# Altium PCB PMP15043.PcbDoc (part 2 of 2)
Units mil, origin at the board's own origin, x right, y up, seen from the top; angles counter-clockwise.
Board outline 3400 x 1800 mil, 4 copper layers (Top Layer, Signal Layer 1, Signal Layer 2, Bottom Layer), stack 60.634 mil thick; 118 components, 63 nets, 326 pads, 97 vias.
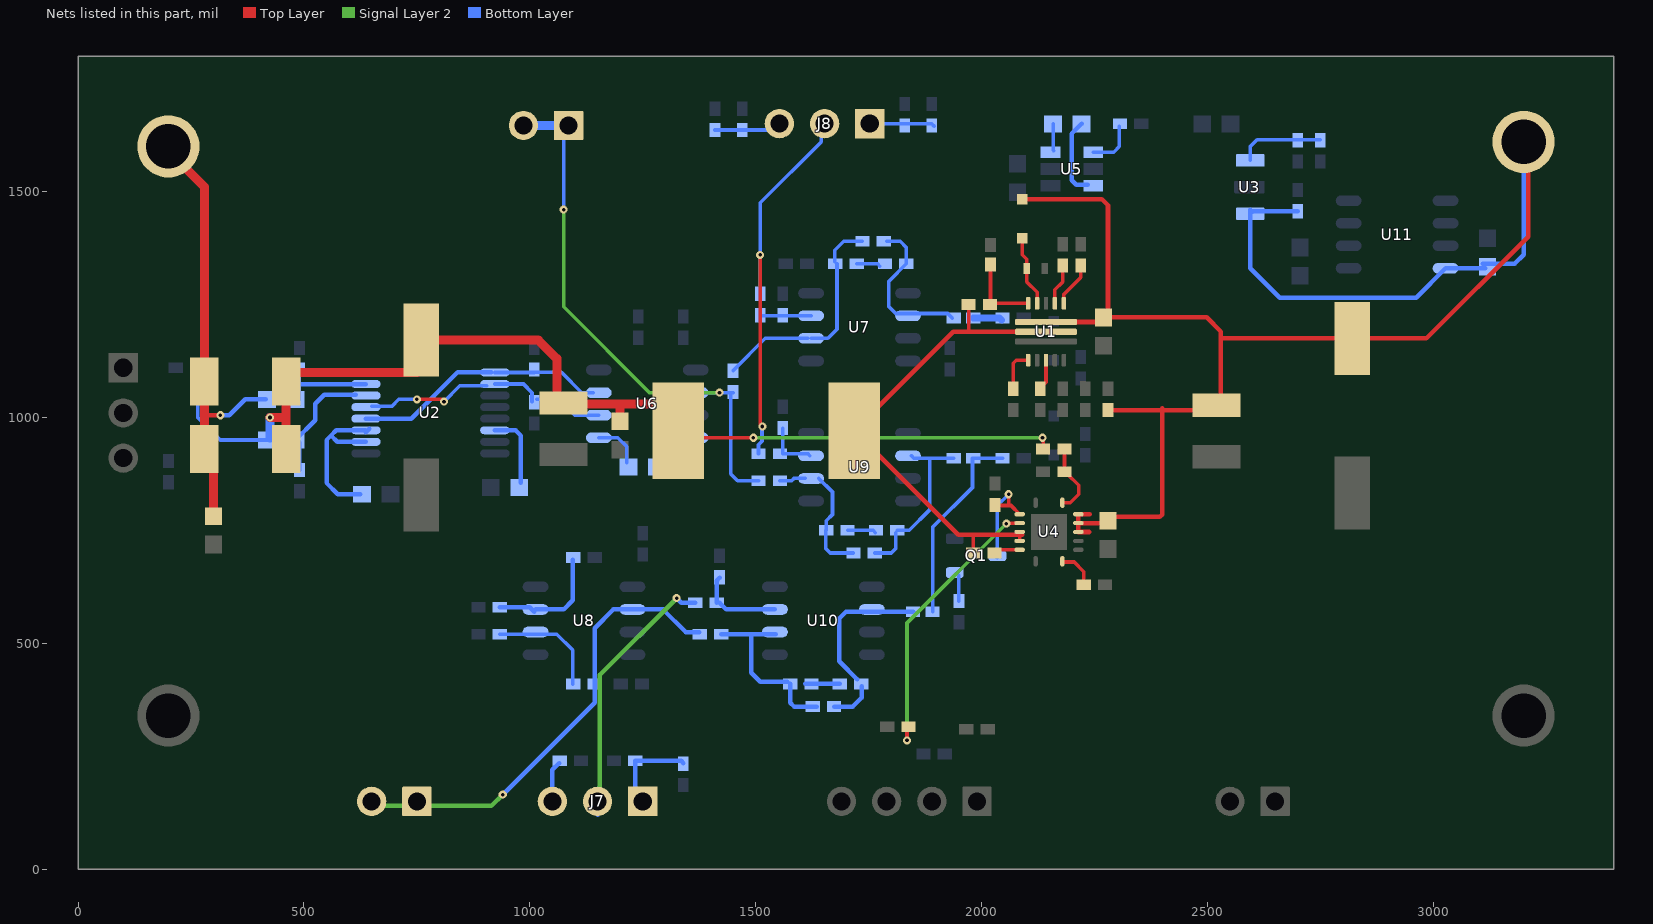
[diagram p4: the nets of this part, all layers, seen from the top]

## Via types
v1: diameter 18, hole 8, Top Layer to Bottom Layer, 93 vias
v2: diameter 19.68, hole 8, Top Layer to Bottom Layer, 4 vias

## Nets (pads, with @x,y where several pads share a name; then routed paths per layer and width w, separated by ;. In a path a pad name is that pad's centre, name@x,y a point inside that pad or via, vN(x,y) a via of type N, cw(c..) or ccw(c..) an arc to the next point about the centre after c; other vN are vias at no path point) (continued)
IBAT: J9.1 J9.2 R23.2 R30.1 U6.6 | length 1259.5
  Signal Layer 2 w8: v1@1075,1465 v1(1075,1460) 1075,1245 1265,1055 v1(1420,1055)
  Bottom Layer w8: v1(1075,1460) J9.1@1075,1635 ; U6.6@1367.28,1055 v1(1420,1055) R23.2@1445,1055 ; R23.2@1450,1055 R23.2@1445,1055 ; R30.1@1506.38,860 1460,860 1445,875 R23.2@1445,1055
  Bottom Layer w20: J9.2@985.91,1646.4 J9.1@1085.91,1646.4 J9.1@1096.4,1646.4
ISEN+: C25.1 U2.1 U2.12 U6.3 | length 556.4
  Bottom Layer w8: U2.1@922.72,1099.57 1009.57,1099.57 1010,1100 1070,1100 1115,1055 U6.3@1140,1055
  Bottom Layer w10: U2.12@637.28,997.2 737.2,997.2 840,1100 U2.1@915,1100
ISEN-: C23.1 U2.2 U2.13 U6.2 | length 533.1
  Top Layer w8: v1(750,1040) v1@805,1040
  Bottom Layer w8: U2.13@650,1025 695,1025 710,1040 v1(750,1040) ; v1(810,1035) 845,1070 U2.2@905,1070 ; U2.2@922.72,1073.98 986.02,1073.98 1005,1055 C23.1@1005,1035 ; C23.1@1015,1040 1065,1040 1100,1005 U6.2@1152.72,1005
ISET: J8.2 R26.2 R36.2 | length 869.5
  Top Layer w8: v1@1510,985 v1(1510,1360)
  Bottom Layer w8: R36.2@1506.38,920 1506.38,939.51 1514,947.13 v1@1514,984 ; R26.2@1510,1273.62 v1(1510,1360) 1510,1475 1645,1610 J8.2@1645,1645
  other v1: 1515,980
NetC3_1: C3.1 J1.1 R1.1 R2.1 R7.2 | length 970.3
  Top Layer w10: 285,1005 v1(315,1005)
  Top Layer w20: J1.1@190,1600 279.45,1510.55 R1.1@279.45,1080 ; R2.1@279.45,930 279.45,1079.45 R1.1@280,1080 ; C3.1@300,781.5 R2.1@300,900
  Bottom Layer w10: v1(315,1005) 335,1005 370,1040 R7.2@415,1040
NetC5_2: C5.2 D1.2 U1.12 | length 156.1
  Top Layer w8: D1.2@2090,1395 2090,1360 2100,1350 C5.2@2100,1330 2100,1300 2123.08,1276.92 U1.12@2123.08,1252.63
NetC6_2: C6.2 D2.1 U1.13 | length 167.8
  Top Layer w8: C6.2@2020,1253.62 2020,1335 D2.1@2025,1340 ; C6.2@2025,1255 2027.37,1252.63 U1.13@2103.39,1252.63
NetC7_1: C7.1 U1.10 | length 84.6
  Top Layer w8: U1.10@2162.45,1252.63 2162.45,1282.45 2180,1300 C7.1@2180,1330
NetC11_1: C11.1 R7.1 U2.15 | length 212.6
  Bottom Layer w8: R7.1@490,1040 C11.1@490,1106.38
  Bottom Layer w10: 491.02,1073.98 U2.15@637.28,1073.98
NetC12_1: C12.1 R8.1 U2.14 | length 257.7
  Bottom Layer w10: R8.1@481.5,950 525,993.5 525,1030 545,1050 585,1050 U2.14@615,1050 ; C12.1@490,883.62 R8.1@490,945
NetC16_1: C16.1 U4.13 | length 50.3
  Top Layer w8: C16.1@2035,705 2037.06,707.06 U4.13@2084.44,707.06
NetC17_1: C17.1 Q1.3 U4.9 | length 234.8
  Top Layer w8: C17.1@2035,810 2040,805 2060,805 ; v1(2060,830) 2060,805 ; U4.9@2084.44,785.8 2065.25,805 2060,805
  Bottom Layer w8: Q1.3@2035,690 2035,735 2035,805 v1(2060,830)
NetC18_1: C18.1 U5.6 | length 173
  Bottom Layer w10: C18.1@2221.5,1650 2200,1628.5 2200,1525 2210,1515 U5.6@2235,1515
NetC18_2: C18.2 U5.3 | length 60.6
  Bottom Layer w8: C18.2@2158.5,1650 2158.5,1591.5 U5.3@2160,1590
NetC20_1: C20.1 C22.1 D3.1 U7.6 | length 347
  Bottom Layer w8: C20.1@1790,1390 1820,1390 1833.62,1376.38 C22.1@1833.62,1340 1795,1301.38 1795,1245 1810,1230 1925,1230 D3.1@1935,1220
NetC20_2: C20.2 R22.1 R23.1 U7.2 | length 499.8
  Bottom Layer w8: R23.1@1450,1103.62 1521.38,1175 U7.2@1615,1175 ; U7.2@1622.72,1175 1660,1175 1680,1195 R22.1@1680,1340 ; R22.1@1675,1345 1675,1370 1695,1390 C20.2@1736.38,1390
NetC22_2: C22.2 R22.2 | length 53.4
  Bottom Layer w8: R22.2@1723.62,1340 1770,1340 C22.2@1775,1335
NetC26_1: C26.1 R26.1 U7.3 | length 112.7
  Bottom Layer w8: R26.1@1510,1225 U7.3@1622.72,1225
NetC28_1: C28.1 C30.1 D5.1 U9.6 | length 386
  Bottom Layer w8: C28.1@1763.62,700 1800,700 1810,710 C30.1@1810,745 ; C30.1@1813.62,750 1840,750 1885,795 1885,910 ; U9.6@1845,915 1850,910 1885,910 ; D5.1@1938.35,910 1885,910
NetC28_2: C28.2 R27.1 R30.2 U9.2 | length 297
  Bottom Layer w8: R30.2@1553.62,860 1580,860 1585,865 U9.2@1610,865 ; U9.2@1640,865 1670,835 1670,785 1656.38,771.38 R27.1@1656.38,750 ; R27.1@1655,750 1655,710 1665,700 C28.2@1716.38,700
NetC29_1: C29.1 C31.1 D7.1 U10.6 | length 415.8
  Bottom Layer w10: C29.1@1673.62,360 1715,360 1735,380 C31.1@1735,405 ; C31.1@1725,420 1685,460 1685,555 1700,570 D7.1@1848.35,570
NetC29_2: C29.2 R31.1 R35.2 U10.2 | length 398.2
  Bottom Layer w10: R35.2@1423.62,520 1490,520 ; U10.2@1545,520 1490,520 ; R31.1@1570,415 1510,415 1490,435 1490,520 ; R31.1@1576.38,410 1576.38,368.62 1585,360 C29.2@1626.38,360 C29.2@1635,360
NetC30_2: C30.2 R27.2 | length 63.4
  Bottom Layer w8: R27.2@1703.62,750 1760,750 C30.2@1765,745
NetC31_2: C31.2 R31.2 | length 76.4
  Bottom Layer w10: R31.2@1610,410 R31.2@1623.62,410 C31.2@1686.38,410
NetC33_1: C33.1 R36.1 U9.3 | length 118.4
  Bottom Layer w8: C33.1@1560,976.38 1560,920 1615,920 U9.3@1620,915
NetC34_1: C34.1 R39.1 U10.3 | length 186.6
  Bottom Layer w10: R39.1@1413.62,590 1413.62,638.62 C34.1@1420,645 ; R39.1@1420,590 1435,575 U10.3@1542.72,575
NetD3_2: D3.2 R25.2 | length 65.4
  Bottom Layer w15: D3.2@1981.65,1220 2040,1220 R25.2@2045,1215
NetD5_2: D5.2 D7.2 R34.2 | length 443
  Bottom Layer w8: D7.2@1891.65,570 1891.65,756.65 1980,845 1980,910 D5.2@1981.65,910 R34.2@2046.38,910
NetJ7_1: J7.1 R42.1 R44.2 | length 182.1
  Bottom Layer w10: J7.1@1233.62,166.38 R42.1@1233.62,240 1335,240 R44.2@1340,235
NetJ7_3: J7.3 R40.1 | length 91.2
  Bottom Layer w10: J7.3@1050,150 1050,220 R40.1@1065,235
NetJ8_1: J8.1 R43.1 R45.2 | length 144.6
  Bottom Layer w8: J8.1@1752.61,1650.34 1889.66,1650.34 R45.2@1895,1645
NetJ8_3: J8.3 R41.1 R46.2 | length 135.6
  Bottom Layer w8: R46.2@1410,1636.38 1526.38,1636.38 J8.3@1540,1650
NetQ1_1: Q1.1 R19.2 | length 56.4
  Bottom Layer w8: R19.2@1950,593.62 Q1.1@1950,650
NetR4_2: R4.2 U1.1 | length 81.1
  Top Layer w8: R4.2@2070,1075 2070,1120 2076.65,1126.65 U1.1@2103.39,1126.65
NetR5_1: R5.1 U1.9 | length 93.1
  Top Layer w8: U1.9@2182.13,1252.63 2182.13,1272.13 2220,1310 R5.1@2220,1330
NetR6_2: R6.2 U1.3 | length 52.8
  Top Layer w8: R6.2@2140,1075 2142.76,1077.76 U1.3@2142.76,1126.65
NetR12_1: R12.1 R13.2 U3.1 | length 192.2
  Bottom Layer w8: U3.1@2594.8,1569.06 2594.8,1599.8 2610,1615 R13.2@2750,1615
NetR14_2: R14.2 U2.10 U2.11 | length 370.6
  Bottom Layer w10: R14.2@625,830 575,830 550,855 550,950 560,960 ; U2.10@637.28,946.02 573.98,946.02 560,960 ; U2.11@637.28,967.28 U2.11@645,975 ; U2.11@637.28,971.61 571.61,971.61 560,960
NetR15_2: R15.2 U2.6 | length 167.1
  Bottom Layer w10: U2.6@922.72,971.61 968.39,971.61 980,960 R15.2@980,855
NetR16_2: R16.2 U4.10 | length 629.5
  Top Layer w8: v1(1835,285) R16.2@1835,315 ; v1@2056.12,766.12 U4.10@2084.44,766.12
  Signal Layer 2 w8: v1(1835,285) 1835,545 v1(2055,765)
NetR17_2: R17.2 R18.2 U4.7 | length 150.6
  Top Layer w8: U4.7@2178.94,811.39 2196.39,811.39 2215,830 2215,850 R18.2@2190,875 ; R18.2@2180,880 2183.62,883.62 R17.2@2183.62,930
NetR20_1: R20.1 U5.4 | length 108
  Bottom Layer w8: U5.4@2247.24,1587.4 2292.4,1587.4 2305,1600 R20.1@2305,1645
NetR21_2: R21.2 U4.1 | length 83.9
  Top Layer w8: U4.1@2180,680 2205,680 2226.38,658.62 2226.38,641.81 R21.2@2226.38,630
NetR24_1: R24.1 U6.8 | length 127.7
  Bottom Layer w8: R24.1@1281.5,890 1281.5,931.5 1300,950 U6.8@1360,950
NetR24_2: R24.2 U6.1 | length 105.6
  Bottom Layer w8: U6.1@1152.72,955 1195,955 1215,935 R24.2@1215,900
NetR29_1: R29.1 R32.2 U8.2 | length 250.9
  Bottom Layer w8: R32.2@933.62,520 1060,520 1095,485 R29.1@1095,410
NetR33_2: R33.2 R38.2 U8.3 | length 261.1
  Bottom Layer w10: R33.2@933.62,580 1000,580 U8.3@1010,570 ; U8.3@1012.72,575 1075,575 1095,595 R38.2@1095,685
SW: C6.1 C16.2 L1.2 U1.7@2142.76,1189.64 U4.11 U4.12 | length 1068.5
  Top Layer w8: 1971.38,1191.38 C6.1@1971.38,1250 ; C16.2@1981.38,700 1981.38,740 1981.38,741.38 ; U4.12@2084.44,726.75 2084.44,740 2084.44,744.44 U4.11@2085,745
  Top Layer w10: 2090,740 2084.44,740 1981.38,740 1948.78,740 L1.2@1718.18,970.59 1937.59,1190 U1.7@2110,1190
VBAT: J12.1 J12.2 R29.2 R35.1 U8.6 | length 1022.5
  Signal Layer 2 w10: J12.2@650,140 750,140 915,140 v1(940,165)
  Bottom Layer w10: v1(940,165) 1143.62,368.62 R29.2@1143.62,410 1143.62,533.62 1185,575 U8.6@1227.28,575 1295,575 1345,525 R35.1@1375,525
VBUS: C8.1 C9.1 C10.1 C13.1 C15.1 C39.1 D1.1 J3.1 R9.2 U1.8@2142.76,1211.29 U3.3 U4.4 U4.5 U4.6 U11.8 | length 3869.7
  Top Layer w10: D1.1@2090,1483.31 2266.69,1483.31 2280,1470 C8.1@2280,1221.5 ; U1.8@2142.76,1211.29 2278.71,1211.29 C8.1@2280,1210 ; U4.6@2214.37,785.8 2239.2,785.8 ; U4.6@2215,785 2214.37,784.37 U4.5@2214.37,766.12 ; 2238.57,746.43 U4.4@2214.37,746.43 U4.5@2214.37,766.12 ; C15.1@2265,765 2263.88,766.12 U4.5@2214.37,766.12 ; C8.1@2270,1221.5 C8.1@2280,1221.5 ; C15.1@2278.5,770 C15.1@2280,771.5 2288.5,780 2395,780 2400,785 2400,1016.38 ; R9.2@2280,1016.38 2400,1016.38 ; C8.1@2280,1220 C8.1@2280,1221.5 ; 2400,1020 2400,1016.38 ; C9.1@2490,1015 2488.62,1016.38 2400,1016.38 ; C9.1@2530,1030 2530,1190 2498.5,1221.5 C8.1@2280,1221.5 ; 2534.86,1174.86 C10.1@2820.96,1174.86 2984.86,1174.86 3210,1400 J3.1@3210,1620
  Bottom Layer w10: U3.3@2595,1460 2595,1330 2660,1265 2962.28,1265 U11.8@3027.28,1330 C39.1@3115,1330 ; U3.3@2600,1455 2601.38,1456.38 C13.1@2700,1456.38 ; C39.1@3110,1340 3180,1340 3200,1360 J3.1@3200,1610
VIN: C1.1 C2.1 C4.1 L1.1 R1.2 R2.2 R8.2 R17.1 R37.1 | length 2316.9
  Top Layer w8: L1.1@1370,955 v1(1495,955) ; R17.1@2136.38,930 v1@2136.38,953.62
  Top Layer w20: v1(425,1000) 460.55,1000 ; R1.2@460,1070 460.55,1069.45 460.55,1000 ; R2.2@460.55,930 460.55,1000 ; R1.2@460.55,1080 480.55,1100 C2.1@750,1100 ; C2.1@760,1171.26 1018.74,1171.26 1060,1130 1060,1030 1200,1030 ; C1.1@1200,991.5 1200,1030 ; L1.1@1330,1030 1200,1030
  Signal Layer 2 w8: v1(1495,955) v1(2135,955)
  Bottom Layer w8: R37.1@265,1110 265,1000 315,950 R8.2@418.5,950
  Bottom Layer w20: R8.2@425,955 v1(425,1000)
VSET: J7.2 R39.2 | length 595.9
  Signal Layer 2 w10: J7.2@1155,150 1155,430 v1(1325,600)
  Bottom Layer w10: J7.2@1150,120 J7.2@1150,150 ; v1(1325,600) 1335,590 R39.2@1366.38,590
pads on no net: J5.2 U1.6@2095.52,1167.98 U1.6@2142.76,1167.98 U1.6@2190.01,1167.98 U1.7@2095.52,1189.64 U1.7@2142.76,1189.64 U1.7@2190.01,1189.64 U1.8@2095.52,1211.29 U1.8@2142.76,1211.29 U1.8@2190.01,1211.29 U2.3 U2.4 U2.5 U4.14 U7.1 U7.5 U7.8 U8.1 U8.5 U8.8 U9.1 U9.5 U9.8 U10.1 U10.5 U10.8 U11.4 U11.5

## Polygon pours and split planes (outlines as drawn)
GND on Top Layer "TOP_LAYER_GND_P036" (solid, remove dead copper, pour order 36): 1960,350 2310,350 2335,375 2335,615 2285,665 1970,665 1945,640 1945,365 1960,350
SW on Top Layer "TOP_LAYER_SW_P034" (solid, remove dead copper, pour order 34): 1645,830 1645,390 1685,350 1865,350 1915,400 1915,815 1910,820
VIN on Top Layer "TOP_LAYER_VIN_P030" (solid, remove dead copper, pour order 30): 1495,865 1495,375 1470,350 1310,350 1265,395 1265,835 1340,910
NetC3_1 on Top Layer "TOP_LAYER_NETC3_1_P000" (solid, remove dead copper, pour order 0): 100,1525 100,1705 150,1755 245,1755 350,1650 350,855 330,835 195,835 185,845 185,1280 100,1365
VIN on Top Layer "TOP_LAYER_VIN_P002" (solid, remove dead copper, pour order 2): 430,875 430,1375 480,1425 1410,1425 1495,1340 1495,835 1460,800 1285,800 1265,820 1265,1005 1245,1025 665,1025 515,875
GND on Top Layer "TOP_LAYER_GND_P004" (solid, remove dead copper, pour order 4): 350,250 160,250 100,310 100,660 165,725 455,725 690,960 1150,960 1160,950 1160,615 795,250
SW on Top Layer "TOP_LAYER_SW_P006" (solid, remove dead copper, pour order 6): 2080,1185 2070,1195 2060,1205 2035,1230 1975,1230 1680,1230 1645,1195 1645,770 1690,725 2085,725 2085,750 2015,750 2000,765 2000,1075 1985,1090 1970,1105 1970,1165 1990,1185 2015,1185
GND on Top Layer "TOP_LAYER_GND_P008" (solid, remove dead copper, pour order 8): 2150,1175 1995,1175 1990,1170 1990,1105 2000,1095 2035,1095 2055,1115 2090,1150 2150,1150 2260,1150 2265,1155 2265,1175
GND on Top Layer "TOP_LAYER_GND_P010" (solid, remove dead copper, pour order 10): 2220,1175 2415,1175 2430,1160 2430,1100 2420,1090 2260,1090 2190,1160
VBUS on Top Layer "TOP_LAYER_VBUS_P012" (solid, remove dead copper, pour order 12): 2075,1205 2075,1225 2080,1230 2190,1230 2240,1280 2240,1415 2255,1430 2805,1430 2805,1215 2795,1205
VBUS on Top Layer "TOP_LAYER_VBUS_P014" (solid, remove dead copper, pour order 14): 2230,740 2230,920 2300,990 2310,1000 2310,1065 2320,1075 2460,1075 2460,815 2385,740
GND on Top Layer "TOP_LAYER_GND_P016" (solid, remove dead copper, pour order 16): 3300,250 3300,790 3150,940 2465,940 2465,800 2440,775 2395,730 2295,730 2260,730 2255,725 2255,675 2255,390 2395,250
VBUS on Top Layer "TOP_LAYER_VBUS_P018" (solid, remove dead copper, pour order 18): 2810,980 3125,980 3305,1160 3305,1665 3270,1700 2385,1700 2240,1555 2240,1390 2335,1295
GND on Bottom Layer "BOTTOM_LAYER_GND_P038" (solid, remove dead copper, pour order 38): 3160,1370 3160,1450 3020,1590 2780,1590 2775,1585 2750,1560 2750,1490 2750,1370 2755,1365
GND on Bottom Layer "BOTTOM_LAYER_GND_P026" (solid, remove dead copper, pour order 26): 3275,290 3275,1110 3150,1235 2335,1235 2265,1165 2265,905 2240,880 2145,880 2120,855 2120,715 2060,655 2060,340 2150,250 3225,250 3275,300
+5V on Bottom Layer "BOTTOM_LAYER_+5V_P020" (solid, remove dead copper, pour order 20): 2545,1505 2545,1610 2535,1620 2330,1620 2325,1615 2325,1390 2345,1370 2535,1370 2550,1385 2550,1505
GND on Signal Layer 2 "SIGNAL_LAYER_2_GND_P022" (solid, remove dead copper, pour order 22): 440,395 440,1260 720,1540 2195,1540 2295,1440 2295,420 2215,340 495,340 440,395
GND on Signal Layer 1 "SIGNAL_LAYER_1_GND_P024" (solid, remove dead copper, pour order 24): 410,390 410,1295 660,1545 2895,1545 2970,1470 2970,395 2880,305 495,305 410,390

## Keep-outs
Keep-Out Layer:
  text ".Layer_Name" at 577,-858.49 h60

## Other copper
Top Layer:
  rectangle net GND: 2240,655 2270,730
  rectangle net VBUS: 2450,980 2830,1220
  rectangle net GND: 2120,830 2190,855
  rectangle net GND: 2135,780 2165,840
  rectangle net GND: 2135,625 2165,715
  rectangle net GND: 2005,505 2195,640
  rectangle net GND: 2260,1090 2390,1175
  text ".Layer_Name" at 577,-858.49 h60
Signal Layer 2:
  pour cut-out: 2285,1195 2360,1195 2375,1180 2375,1085 2365,1075 2295,1075 2285,1085
  pour cut-out: 1990,1185 2070,1185 2080,1175 2080,1115 2060,1095 2005,1095 1990,1110
  pour cut-out: 2215,580 2215,835 2195,855 2095,855 2085,845 2085,660 2065,640 2065,590 2075,580
  pour cut-out: 1015,880 1030,895 1130,895 1140,885 1140,830 1130,820 1020,820 1015,825
Bottom Layer:
  rectangle net GND: 1030,830 1135,880
  rectangle net GND: 2110,580 2205,790
  rectangle net GND: 2075,580 2205,665
  rectangle net GND: 2120,735 2205,855
  rectangle net GND: 1975,1045 2095,1175
  text ".Layer_Name" at 577,-858.49 h60

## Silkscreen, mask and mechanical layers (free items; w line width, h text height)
Top Overlay:
  rectangle: 2050,1100 2070,1120
  rectangle: 2240,655 2260,670
  lines w10: 1530,15 1730,15 1790,75 1790,95 ; 1890,95 1890,70 1940,20 2215,20
  text "VBUS" at 2890,1580 h80
  text "BAT" at 325,1555 h80
  text "H" at 1525,1540 h60
  text "ISET" at 1600,1540 h60
  text "L" at 1745,1540 h60
  text "IBAT" at 980,1535 h60
  text "B+" at 75,1175 h60
  text "B-" at 75,810 h60
  text "GND" at 325,320 h80
  text "GND" at 2935,315 h80
  text "VBAT" at 640,220 h60
  text "VSET" at 1090,220 h60
  text "L" at 1250,220 h60
  text "5V" at 1640,220 h60
  text "H" at 1030,215 h60
  text "GND" at 1965,215 h60
  text "GND" at 2540,215 h60
  text "BUCK_EN" at 1960,40 h60
  text "BST_EN" at 1525,35 h60
  text ".Layer_Name" at 577,-858.49 h60
Bottom Overlay:
  rectangle: 1465,435 1505,475
  rectangle: 1530,740 1585,785
  rectangle: 1540,1115 1580,1160
  rectangle: 920,420 970,470
  rectangle: 1060,895 1110,945
  rectangle: 900,1155 955,1210
  text ".Layer_Name" at 577,-858.49 h60
Top Paste:
  text ".Layer_Name" at 577,-858.49 h60
Bottom Paste:
  text ".Layer_Name" at 577,-858.49 h60
Top Solder:
  text ".Layer_Name" at 577,-858.49 h60
  text ".Layer_Name" at 577,-858.49 h60
Bottom Solder:
  text ".Layer_Name" at 577,-858.49 h60
Drill Guide:
  text ".Layer_Name" at 577,-858.49 h60
M1 Board Outline:
  lines w2: 0,0 2950,0 3400,0 3400,1800 0,1800
  lines w5: 0,0 0,1800
  text ".Layer_Name" at 577,-858.49 h60
M2 Board Dimensions:
  rectangle: 0,-275 125,-150
  rectangle: 125,-400 500,-275
  lines w7: 0,-275 1000,-275 ; 125,-400 125,-150 ; 250,-400 250,-150 ; 500,-400 500,-150 ; 750,-400 750,-150 ; 0,-400 1000,-400 1000,-150 0,-150 0,-400
  text ".Layer_Name" at 577,-858.49 h60
M3 3D STEP Top:
  text ".Layer_Name" at 577,-858.49 h60
M4 3D STEP Bottom:
  text ".Layer_Name" at 577,-858.49 h60
M5 Assembly Top:
  lines w10: -292,-930.17 6308,-930.17 ; -292,-726.83 6310,-726.83 ; -292,-523.5 -292,-1133.5 3713,-1133.5 6310,-1133.5 6310,-523.5 -291.5,-523.5 -291.5,-1133.5 1284,-1133.5 ; 2173,-1133.5 2173,-523.5 ; 3440,-726.83 3440,-523.5 ; 4280,-726.83 4280,-523.5 ; 4902,-1140 4902,-937.17
  text "COMPONENTS MARKED 'DNP' SHOULD NOT BE POPULATED." at 1153.5,-318.5 h60
  text "ASSEMBLY VARIANT:" at 1153,-434 h60
  text ".VariantName" at 2189,-434 h60
  text "PCB VIEWED FROM TOP SIDE" at -228.5,-655.67 h60
  text "BOARD #:" at 2248,-655.67 h60
  text ".PRJ_Number" at 2793.5,-655.67 h60
  text "REV:" at 3638,-655.67 h60
  text ".PCB_Rev" at 3929.5,-655.67 h60
  text "SVN REV:" at 4476,-655.67 h60
  text ".VersionControl_RevNumber" at 4982,-655.67 h60
  text "TID #:" at 2248,-859 h60
  text ".TID" at 2793.5,-859 h60
  text "PLOT NAME =" at -228.5,-1064.34 h60
  text ".plot_File_Name" at 577,-1064.34 h60
  text "GENERATED    :" at 2250,-1064.34 h60
  text ".Print_Date" at 3119.5,-1064.34 h60
  text ".Print_Time" at 3848.5,-1064.34 h60
  text "TEXAS INSTRUMENTS" at 5113,-1064.34 h60
M6 Assembly Bottom:
  lines w10: -292.5,-727.33 6309.5,-727.33 ; -290.5,-930.67 6309.5,-930.67 ; 1115.5,-1140.5 1115.5,-937.67 ; 1737.5,-727.33 1737.5,-524 ; 2577.5,-727.33 2577.5,-524 ; 3844.5,-1134 3844.5,-524 ; 4733.5,-1134 6309,-1134 6309,-524 -292.5,-524 -292.5,-1134 2304.5,-1134 6309.5,-1134 6309.5,-524
  text "COMPONENTS MARKED 'DNP' SHOULD NOT BE POPULATED." at 6102,-318 h60
  text ".VariantName" at 5058,-434 h60
  text "ASSEMBLY VARIANT:" at 6097,-434 h60
  text ".VersionControl_RevNumber" at 1035.5,-656.17 h60
  text "SVN REV:" at 1541.5,-656.17 h60
  text ".PCB_Rev" at 2088,-656.17 h60
  text "REV:" at 2379.5,-656.17 h60
  text ".PRJ_Number" at 3224,-656.17 h60
  text "BOARD #:" at 3769.5,-656.17 h60
  text "PCB VIEWED FROM BOTTOM SIDE" at 6246,-656.17 h60
  text ".TID" at 3224,-859.5 h60
  text "TID #:" at 3769.5,-859.5 h60
  text "TEXAS INSTRUMENTS" at 904.5,-1064.84 h60
  text ".Print_Time" at 2169,-1064.84 h60
  text ".Print_Date" at 2898,-1064.84 h60
  text "GENERATED    :" at 3767.5,-1064.84 h60
  text ".plot_File_Name" at 5440.5,-1064.84 h60
  text "PLOT NAME =" at 6246,-1064.84 h60
M9 Title Sheet:
  drawing of 57 lines, arcs and shapes, not listed
  text "1" at 739.84,8036.5 h70
  text "2" at 3235.5,8036.5 h70
  text "3" at 5724.84,8036.5 h70
  text "4" at 8231.51,8036.5 h70
  text "5" at 10730.5,8036.5 h70
  text "6" at 13235.5,8036.5 h70
  text "A" at -416.5,6893.5 h70
  text "A" at 14383.5,6893.5 h70
  text "B" at -416.5,4513.5 h70
  text "B" at 14383.5,4513.5 h70
  text "C" at -416.5,2138.5 h70
  text "C" at 14383.5,2138.5 h70
  text "PROJECT TITLE:" at 11343.5,277.5 h45
  text ".PRJ_Title" at 11393.5,144.17 h70
  text "DESIGNED FOR:" at 11343.5,-23.5 h45
  text ".PRJ_Customer" at 11393.5,-163.5 h70
  text "D" at -416.5,-231.5 h70
  text "D" at 14383.5,-231.5 h70
  text "FILE NAME:" at 11343.5,-323.5 h45
  text ".PCB_File_Name_No_Path" at 11393.5,-443.5 h70
  text "Texas Instruments (TI) and/or its licensors do not warrant the accuracy or completeness of this specification" at 6374,-605.34 h45
  text "ENGINEER:" at 11343.5,-613.5 h45
  text "LAYOUT BY:" at 12848.5,-613.5 h45
  text "or any information contained therein. TI and/or its licensors do not warrant that this design will meet" at 6329.01,-718 h45
  text ".PRJ_Engineer" at 11393.5,-768.49 h70
  text ".PCB_Layout" at 12899,-768.49 h70
  text "the specifications, will be suitable for your application or fit for any particular purpose, or will operate in" at 6329.01,-830.67 h45
  text ".Layer_Name" at 577,-858.49 h60
  text "ALTIUM DESIGNER VERSION:" at 12848.5,-923.5 h45
  text "an implementation. TI and/or its licensors do not warrant that the design is production worthy. You should" at 6329.01,-943.33 h45
  text "completely validate and test your design implementation to confirm the system functionality for your application." at 6374,-1056 h45
  text ".print_Scale" at 11393.5,-1056.83 h70
  text ".Application_BuildNumber" at 12899,-1056.83 h70
  text "1" at 739.84,-1263.5 h70
  text "2" at 3235.5,-1263.5 h70
  text "3" at 5724.84,-1263.5 h70
  text "4" at 8231.51,-1263.5 h70
  text "5" at 10730.5,-1263.5 h70
  text "6" at 13235.5,-1263.5 h70
M10 Fab Notes:
  drawing of 173 lines, arcs and shapes, not listed
  text "DESIGN INFORMATION" at 12378.02,6201 h60
  text "MIN. TRACK WIDTH:" at 11733.46,6021 h60
  text "8" at 12829.7,6021 h60
  text "MIL" at 12984.46,6021 h60
  text "MIN. CLEARANCE:" at 11733.46,5889 h60
  text "0.2" at 12769.7,5889 h60
  text "mm" at 12984.46,5889 h60
  text "MIN. VIA PAD SIZE:" at 11733.46,5757 h60
  text "24" at 12799.71,5757 h60
  text "MIL" at 12984.46,5757 h60
  text "0.05mm (2MIL)" at 12428.46,5615.29 h60
  text "MINIMUM ANNULAR RING" at 11404.23,5611 h60
  text "EXTERNAL" at 13136.46,5611 h60
  text "PER" at 11604.23,5493 h60
  text "IPC-D-275 CLASS 2 LEVEL C" at 11824.23,5493 h60
  text "MIL, HOLES" at 13312.46,5380.71 h60
  text "+/-" at 12920,5380 h60
  text "+/-" at 13774,5380 h60
  text "REGISTRATION TOLERANCES:" at 11404.23,5375 h60
  text "METAL" at 12604,5375 h60
  text "5" at 13180.2,5375 h60
  text "3" at 14013.2,5375 h60
  text "MIL" at 14129.46,5375 h60
  text "+/-" at 13774,5262 h60
  text "HOLE SIZE TOLERANCE (UNLESS OTHERWISE SPECIFIED):" at 11404.23,5257 h60
  text "3" at 14013.2,5257 h60
  text "MIL" at 14129.46,5257 h60
  text "MATERIAL:" at 11329.46,5047.54 h60
  text "FR-4 High Tg" at 12315.9,4907.21 h60
  text "FR-408" at 11750.46,4898.64 h60
  text "OTHER" at 13238.46,4898.64 h60
  text "X" at 12161,4895 h60
  text "62 MIL (1.6mm) +/-10%" at 12070.56,4735.92 h60
  text "THICKNESS:" at 11404.23,4731.64 h60
  text "X" at 11942.4,4731.64 h60
  text "OTHER" at 13355.46,4731.64 h60
  text "TOLERANCE:" at 11404.23,4573.64 h60
  text "X" at 12243.53,4573.64 h60
  text "ANSI IPC-6012 TYPE 3 CLASS 2" at 12430.48,4573.64 h60
  text "OTHER +/-" at 12430.46,4417.64 h60
  text "BOW & TWIST:" at 11404.23,4260.64 h60
  text "X" at 12243.53,4260.64 h60
  text "ANSI IPC-6012 TYPE 3 CLASS 2" at 12430.48,4260.64 h60
  text "OTHER +/-" at 12430.46,4102.13 h60
  text "DRILLING:" at 11329.46,3963.64 h60
  text "REFERENCE:" at 11404.23,3846.64 h60
  text "X" at 12052.46,3846.64 h60
  text "AS SHOWN" at 12239.46,3846.64 h60
  text "X" at 12953.46,3846.64 h60
  text "NC_DRILL FILES" at 13090.46,3846.64 h60
  text "PTH COPPER THICKNESS:" at 11404.23,3688.64 h60
  text "X" at 12534.46,3688.64 h60
  text "20-30 um" at 12671.46,3688.64 h60
  text "OTHER" at 13388.46,3688.64 h60
  text "BOARD FINISH:" at 11329.46,3529.64 h60
  text "SILKSCREEN:" at 11484.68,3411.64 h60
  text "X" at 12433.46,3411.64 h60
  text "TOP" at 12559.46,3411.64 h60
  text "X" at 12943.46,3411.64 h60
  text "BOTTOM" at 13070.46,3411.64 h60
  text "SILKSCREEN COLOR:" at 11484.68,3244.64 h60
  text "X" at 12432.42,3244.64 h60
  text "WHITE" at 12559.46,3244.64 h60
  text "OTHER" at 13070.46,3244.64 h60
  text "X" at 12563.42,3085.44 h60
  text "GREEN" at 12690.46,3085.44 h60
  text "OTHER" at 13308.46,3085.44 h60
  text "SOLDER RESIST COLOR:" at 11484.68,3074.64 h60
  text "X" at 12563.42,2915.44 h60
  text "MATTE" at 12690.46,2915.44 h60
  text "SEMI-GLOSS" at 13308,2914.8 h60
  text "IMMERSION GOLD (ENIG)" at 12390.46,2726.92 h60
  text "ENEPIG" at 13728,2723.64 h60
  text "SURFACE FINISH:" at 11329.46,2722.64 h60
  text "X" at 12203.51,2722.64 h60
  text "IMM. TIN/SILVER OR EQUIV" at 11659,2565.64 h60
  text "OTHER" at 13090.46,2565.64 h60
  text "ARRAY/PANEL:" at 11329.46,2386.64 h60
  text "CUT AND TRIM PER M1 BOARD OUTLINE" at 12390.46,2382.35 h60
  text "N.C. ROUTE" at 12390.46,2230.64 h60
  text "X" at 13069.46,2230.64 h60
  text "V. SCORE" at 13256.46,2230.64 h60
  text "CERTIFICATION:" at 11329.46,2093.64 h60
  text "MATERIALS AND WORKMANSHIP FOR ALL PCBS" at 12054.46,2093.64 h60
  text "TO MEET OR EXCEED THE REQUIREMENTS OF:" at 12054.46,1995.64 h60
  text "X" at 11680.96,1859.13 h60
  text "ANSI IPC-A-600F CLASS ->" at 11819.96,1859.13 h60
  text "X" at 13459.02,1859.13 h60
  text "2" at 13577.96,1859.14 h60
  text "1" at 13262.96,1857.64 h60
  text "3" at 13931.96,1857.64 h60
  text "X" at 12495.02,1699.64 h60
  text "RoHS" at 12631.96,1699.64 h60
  text "OTHER" at 13276.36,1699.64 h60
  text "PER ORDER" at 13673.42,1699.64 h60
  text "ALL BOARDS MUST MEET OR EXCEED UL94-V0 REQUIREMENTS." at 11357,1534 h60
  text "PCB MUST BEAR THE UL94V-0 UL REGISTERED MATERIAL ID NUMBER" at 11357,1414 h60
  text "ADDITIONAL REQUIREMENTS:" at 11329.46,1240.64 h60
  text "MICROSECTION:" at 11404.23,1125.64 h60
  text "YES" at 12309.96,1125.64 h60
  text "REQUIRED" at 13171.46,969.49 h60
  text "BARE BOARD ELEC. TEST:" at 11404.23,966.64 h60
  text "NONE" at 12709.96,966.64 h60
  text "X" at 13044.46,966.64 h60
  text "PER ORDER" at 13763.46,966.64 h60
  text ".Layer_Name" at 577,-858.49 h60
M11 Gerber Information:
  lines w10: -292,-930.17 6308,-930.17 ; -292,-726.83 6310,-726.83 ; -292,-523.5 -292,-1133.5 3713,-1133.5 6310,-1133.5 6310,-523.5 -291.5,-523.5 -291.5,-1133.5 1284,-1133.5 ; 2173,-1133.5 2173,-523.5 ; 3440,-726.83 3440,-523.5 ; 4280,-726.83 4280,-523.5 ; 4902,-1140 4902,-937.17
  text "ALL ARTWORK VIEWED FROM TOP SIDE" at -228.5,-655.67 h60
  text "BOARD #:" at 2248,-655.67 h60
  text ".PRJ_Number" at 2793.5,-655.67 h60
  text "REV:" at 3638,-655.67 h60
  text ".PCB_Rev" at 3929.5,-655.67 h60
  text "SVN REV:" at 4476,-655.67 h60
  text ".VersionControl_RevNumber" at 4982,-655.67 h60
  text "LAYER NAME =" at -228.5,-858.49 h60
  text "TID #:" at 2248,-859 h60
  text ".TID" at 2793.5,-859 h60
  text "PLOT NAME =" at -228.5,-1064.34 h60
  text ".plot_File_Name" at 577,-1064.34 h60
  text "GENERATED    :" at 2250,-1064.34 h60
  text ".Print_Date" at 3119.5,-1064.34 h60
  text ".Print_Time" at 3848.5,-1064.34 h60
  text "TEXAS INSTRUMENTS" at 5113,-1064.34 h60
M12 Stackup:
  drawing of 295 lines, arcs and shapes, not listed
  text "Layer" at 9797.84,7830 h60
  text "Name" at 10207.76,7830 h60
  text "Material" at 11147.5,7830 h60
  text "Thickness" at 12007.26,7830 h60
  text "Constant" at 12657.1,7830 h60
  text "Board Layer Stack" at 13226.96,7830 h60
  text "1" at 9797.84,7710 h60
  text "Top Overlay" at 10207.76,7710 h60
  text "2" at 9797.84,7590 h60
  text "Top Solder" at 10207.76,7590 h60
  text "Solder Resist" at 11147.5,7590 h60
  text "0.40mil" at 12007.26,7590 h60
  text "3.5" at 12657.1,7590 h60
  text "3" at 9797.84,7470 h60
  text "Top Layer" at 10207.76,7470 h60
  text "Copper" at 11147.5,7470 h60
  text "1.40mil" at 12007.26,7470 h60
  text "4" at 9797.84,7350 h60
  text "Dielectric 2" at 10207.76,7350 h60
  text "5.00mil" at 12007.26,7350 h60
  text "4.2" at 12657.1,7350 h60
  text "5" at 9797.84,7230 h60
  text "Signal Layer 1" at 10207.76,7230 h60
  text "Copper" at 11147.5,7230 h60
  text "1.42mil" at 12007.26,7230 h60
  text "6" at 9797.84,7110 h60
  text "Dielectric 3" at 10207.76,7110 h60
  text "FR-4" at 11147.5,7110 h60
  text "45.00mil" at 12007.26,7110 h60
  text "4.2" at 12657.1,7110 h60
  text "7" at 9797.84,6990 h60
  text "Signal Layer 2" at 10207.76,6990 h60
  text "Copper" at 11147.5,6990 h60
  text "1.42mil" at 12007.26,6990 h60
  text "8" at 9797.84,6870 h60
  text "Dielectric1" at 10207.76,6870 h60
  text "5.00mil" at 12007.26,6870 h60
  text "4.2" at 12657.1,6870 h60
  text "9" at 9797.84,6750 h60
  text "Bottom Layer" at 10207.76,6750 h60
  text "Copper" at 11147.5,6750 h60
  text "1.40mil" at 12007.26,6750 h60
  text "10" at 9797.84,6630 h60
  text "Bottom Solder" at 10207.76,6630 h60
  text "Solder Resist" at 11147.5,6630 h60
  text "0.40mil" at 12007.26,6630 h60
  text "3.5" at 12657.1,6630 h60
  text "11" at 9797.84,6510 h60
  text "Bottom Overlay" at 10207.76,6510 h60
  text ".Layer_Name" at 577,-858.49 h60
M13 Component Bodies Top:
  text ".Layer_Name" at 577,-858.49 h60
M14 Component Bodies Bottom:
  text ".Layer_Name" at 577,-858.49 h60
M15 Courtyards Top:
  text ".Layer_Name" at 577,-858.49 h60
M16 Courtyards Bottom:
  text ".Layer_Name" at 577,-858.49 h60
Drill Drawing:
  text ".Layer_Name" at 577,-858.49 h60
M17 Embedded Cavity:
  text ".Layer_Name" at 577,-858.49 h60
M18 Embedded Assembly:
  text ".Layer_Name" at 577,-858.49 h60
M19 Embedded Keepout:
  text ".Layer_Name" at 577,-858.49 h60

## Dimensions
0,-400 to 1000,-400 on M2 Board Dimensions
0,0 to 0,1800 on M2 Board Dimensions
0,0 to 3400,-15 on M2 Board Dimensions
